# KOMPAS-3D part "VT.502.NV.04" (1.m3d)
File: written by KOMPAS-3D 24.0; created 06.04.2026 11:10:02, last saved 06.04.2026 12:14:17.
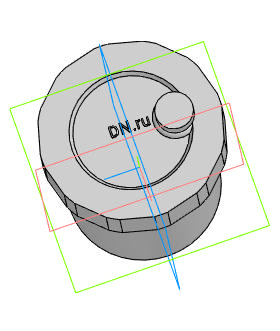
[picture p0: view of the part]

Document properties: Автор: R2D2; Полное имя файла: E:\Работа\Зайцев\Солянка\AV00E-T Воздухоотводчик DN.ru\Ду15 Ру10\исходные материалы\1.m3d

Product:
- Body: Твердое тело1  | qty 1
    Масса: 0.482526
- Part/product: VT.502.NV.04
    Масса: 0.482526
    additional columns: Типовые

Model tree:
1. Твердое тело1  (labels: Твердое тело1)
2. Эскиз:1  (labels: Грань.Твердое тело1)
3. Элемент выдавливания:1
     Расстояние 1 = 0.5
4. Эскиз:3
5. Элемент выдавливания:3
     Расстояние 1 = 100
6. Эскиз:4  (labels: Ребро.Твердое тело1)
7. Элемент выдавливания:4
     Расстояние 1 = 50
8. Эскиз:5  (with: Грань.Элемент выдавливания:1)
9. Элемент выдавливания:5
     Расстояние 1 = 0.5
